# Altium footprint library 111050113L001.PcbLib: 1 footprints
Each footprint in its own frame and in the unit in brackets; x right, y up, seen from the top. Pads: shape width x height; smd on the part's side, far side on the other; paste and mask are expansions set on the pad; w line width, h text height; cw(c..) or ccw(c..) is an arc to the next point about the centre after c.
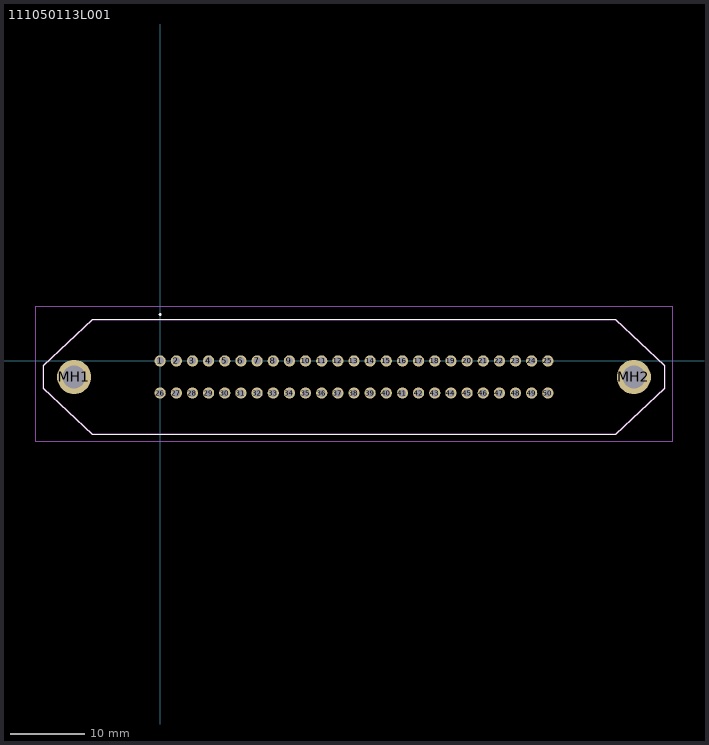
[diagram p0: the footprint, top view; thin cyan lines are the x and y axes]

## 111050113L001 [mm]
pads (52):
  round 1.5 hole 1: 1(0,0) 2(2.16,0) 3(4.32,0) 4(6.48,0) 5(8.64,0) 6(10.8,0) 7(12.96,0) 8(15.12,0) 9(17.28,0) 10(19.44,0) 11(21.6,0) 12(23.76,0) 13(25.92,0) 14(28.08,0) 15(30.24,0) 16(32.4,0) 17(34.56,0) 18(36.72,0) 19(38.88,0) 20(41.04,0) 21(43.2,0) 22(45.36,0) 23(47.52,0) 24(49.68,0) 25(51.84,0) 26(0,-4.29) 27(2.16,-4.29) 28(4.32,-4.29) 29(6.48,-4.29) 30(8.64,-4.29) 31(10.8,-4.29) 32(12.96,-4.29) 33(15.12,-4.29) 34(17.28,-4.29) 35(19.44,-4.29) 36(21.6,-4.29) 37(23.76,-4.29) 38(25.92,-4.29) 39(28.08,-4.29) 40(30.24,-4.29) 41(32.4,-4.29) 42(34.56,-4.29) 43(36.72,-4.29) 44(38.88,-4.29) 45(41.04,-4.29) 46(43.2,-4.29) 47(45.36,-4.29) 48(47.52,-4.29) 49(49.68,-4.29) 50(51.84,-4.29)
  round 4.575 hole 3.05: MH1(-11.505,-2.145) MH2(63.345,-2.145)
Top Overlay:
  lines w0.1: -15.63,-3.645 -15.63,-0.645 -9.08,5.505 60.92,5.505 67.47,-0.645 67.47,-3.645 60.92,-9.795 -9.08,-9.795 -15.63,-3.645
  lines w0.2: -0.1,6.2 -0.1,6.2 ; -0.1,6.2 cw(c0,6.2) 0.1,6.2 ; -0.1,6.2 ccw(c0,6.2) 0.1,6.2 ; 0.1,6.2 0.1,6.2
Mechanical 15:
  lines w0.2: -15.63,-3.645 -15.63,-0.645 -9.08,5.505 60.92,5.505 67.47,-0.645 67.47,-3.645 60.92,-9.795 -9.08,-9.795 -15.63,-3.645
Mechanical 20:
  lines w0.1: -16.63,-10.795 68.47,-10.795 68.47,7.3 -16.63,7.3 -16.63,-10.795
